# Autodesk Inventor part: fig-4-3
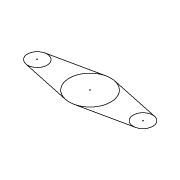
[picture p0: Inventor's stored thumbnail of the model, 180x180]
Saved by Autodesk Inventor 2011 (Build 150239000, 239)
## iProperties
Created: 2005-02
Part Number: fig-4-3
Document SubType Name: Modeling
Designer: CADCIM
Manufacturer: Standard
Standards Organization: Custom
Density: 1 g/cm^3
Author: CADCIM
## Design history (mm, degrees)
sketch "Sketch1"
  geometry: L1 (-33.874, 5.844)-(-2.722, 12.469); L2 (2.595, 12.472)-(33.871, 5.852); L3 (-33.884, -5.902)-(-2.745, -12.585); L4 (2.595, -12.592)-(33.871, -5.972); A1 r 12.81 centre (-0.057, -0.06) between (-2.722, 12.469) and (2.595, 12.472); A2 r 6.006 centre (-32.624, -0.03) between (-33.874, 5.844) and (-33.884, -5.902); A3 r 6.043 centre (32.619, -0.06) between (33.871, 5.852) and (33.871, -5.972)
  constraints: 8 end point, 8 point on circle, 8 tangent, 3 centre point, 1 other
